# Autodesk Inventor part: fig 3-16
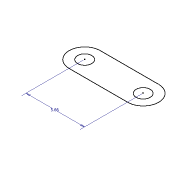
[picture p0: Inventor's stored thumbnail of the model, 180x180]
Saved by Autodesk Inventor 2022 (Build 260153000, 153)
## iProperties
Created: 2009-11
Part Number: fig 3-16
Document SubType Name: Modeling
Designer: Sham
Density: 1 g/cm^3
Material: Generic
Appearance: Default
Author: Sham
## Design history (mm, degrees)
sketch "Sketch1"
  geometry: L1 (4.59, -0.041)-(10.25, -0.041); L2 (4.59, -3.041)-(10.25, -3.041); C1 r 0.679 at (4.59, -1.541); C2 r 0.679 at (10.25, -1.541); A1 r 1.5 centre (4.59, -1.541) between (4.59, -0.041) and (4.59, -3.041); A2 r 1.5 centre (10.25, -1.541) between (10.25, -3.041) and (10.25, -0.041)
  constraints: 4 centre point, 4 end point, 4 point on circle, 2 coincident, 2 horizontal, 2 tangent, 1 equal radius
  dimensions: "d2" = 5.66 dimension on A1.centre A1 A2.centre A2 L1.start L1.end L1 L2.start L2.end L2 C1.centre C1 C2.centre C2; "d2" = 5.66 distance of A2.centre A1.centre
